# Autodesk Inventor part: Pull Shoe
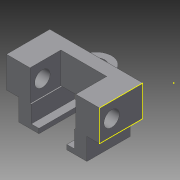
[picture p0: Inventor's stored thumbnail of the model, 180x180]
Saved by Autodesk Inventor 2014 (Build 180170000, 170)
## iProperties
Created: 2013-11
Part Number: Pull Shoe
Material: Generic
Document SubType Name: Modeling
Designer: 603839
Density: 1 g/cm^3
Appearance: Default
Mass: 5.74904 g
Surface Area: 34.2005 cm^2
Volume: 5.74904 cm^3
Author: 603839
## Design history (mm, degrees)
sketch "Sketch1"
  geometry: L1 (-19.05, -6.35)-(19.05, -6.35); L2 (19.05, -6.35)-(19.05, 6.35); L3 (19.05, 6.35)-(-19.05, 6.35); L4 (-19.05, 6.35)-(-19.05, -6.35); L5 (-19.05, -6.35)-(19.05, 6.35); L6 (19.05, -6.35)-(-19.05, 6.35); 1 further point
  constraints: 12 end point, 2 midpoint, 2 parallel, 1 horizontal, 1 perpendicular
  dimensions: "d0" = 38.1 distance of L1.start L1.end; "d1" = 12.7 distance of L2.end L1.end
extrude "Extrusion1" new body sketch "Sketch1" distance "d2" = 25.4; taper "d3" = 0 deg
sketch "Sketch6"
  geometry: L1 (38.1, 0)-(38.1, -25.4) reference; L2 (38.1, 0)-(0, 0) reference; L3 (0, 0)-(0, -25.4) reference; A1 r 20.637 centre (19.05, -20.637) between (38.1, -12.7) and (0, -12.7); 1 further point
  constraints: 3 point on circle, 2 midpoint, 1 centre point
extrude "Extrusion4" cut sketch "Sketch6" distance "d15" = 25.4; taper "d16" = 0 deg
sketch "Sketch7"
  geometry: C1 r 3.175 at (19.05, 25.4); C2 r 5.08 at (19.05, 25.4); 1 further point
  constraints: 2 centre point, 2 coincident
  dimensions: "d17" = 6.35 diameter of C1; "d18" = 10.16 diameter of C2
extrude "Extrusion5" join sketch "Sketch7" distance "d19" = 12.7; taper "d20" = 0 deg
sketch "Sketch8"
  geometry: A1 r 20.637 centre (19.05, 4.763) between (14.009, 24.775) and (0, 12.7) reference; A2 r 20.637 centre (19.05, 4.763) between (38.1, 12.7) and (24.091, 24.775) reference; A3 r 5.08 centre (19.05, 25.4) between (24.091, 24.775) and (14.009, 24.775) reference; A4 r 3.175 centre (19.05, 25.4) between (22.216, 25.156) and (15.884, 25.156) reference; A5 r 20.637 centre (19.05, 4.763) between (22.216, 25.156) and (15.884, 25.156) reference; A6 r 3.175 centre (19.05, 25.4) between (22.216, 25.156) and (15.884, 25.156); A7 r 5.08 centre (19.05, 25.4) between (24.091, 24.775) and (14.009, 24.775); A8 r 20.637 centre (19.05, 4.763) between (24.091, 24.775) and (14.009, 24.775)
  constraints: 13 point on circle, 3 centre point, 3 concentric, 2 coincident
extrude "Extrusion6" cut sketch "Sketch8" distance "d21" = 6.35; taper "d22" = 0 deg
sketch "Sketch13"
  geometry: L1 (18.796, -23.136)-(18.796, 0) reference; L2 (0, 0)-(18.796, 0); L3 (18.796, 0)-(18.796, -7.62); L4 (18.796, -7.62)-(0, -7.62); L5 (0, -7.62)-(0, 0); 1 further point
  constraints: 8 end point, 2 parallel, 1 horizontal, 1 perpendicular, 1 point on line
  dimensions: "d29" = 7.62 distance of L2.end L3.end
extrude "Extrusion10" cut sketch "Sketch13" stored distance "d30" = 2.54; taper "d31" = 0 deg
sketch "Sketch18"
  geometry: L1 (-9.398, -4.763)-(-19.05, -4.763) reference; L2 (-19.05, 7.937)-(19.05, 7.937); A1 r 20.637 centre (0, 0) between (19.05, 7.937) and (-19.05, 7.937) reference; A2 r 20.637 centre (0, 0) between (19.05, 7.937) and (-19.05, 7.937); 1 further point
  constraints: 3 point on circle, 2 end point, 1 centre point, 1 concentric, 1 parallel
extrude "Extrusion13" cut sketch "Sketch18" stored distance "d47" = 2.54; taper "d49" = 0 deg
sketch "Sketch19"
  geometry: A1 r 3.175 centre (19.05, 25.4) between (22.216, 25.156) and (15.884, 25.156) reference; A2 r 20.637 centre (19.05, 4.763) between (24.091, 24.775) and (22.216, 25.156) reference; A3 r 5.08 centre (19.05, 25.4) between (24.091, 24.775) and (14.009, 24.775) reference; A4 r 20.637 centre (19.05, 4.763) between (15.884, 25.156) and (14.009, 24.775) reference
extrude "Extrusion14" cut sketch "Sketch19" stored distance "d50" = 0; taper "d51" = 0 deg
sketch "Sketch21"
  geometry: L1 (28.448, 5.08)-(-9.652, 5.08) reference; L2 (0, 0)-(18.796, 0) reference; C1 r 3.175 at (9.398, 5.398); A1 r 6.35 centre (9.398, 5.08) between (13.208, 0) and (5.588, 0); 1 further point
  constraints: 2 centre point, 2 point on circle, 2 point on line, 1 midpoint
  dimensions: "d52" = 12.7 diameter of A1; "d53" = 6.35 diameter of C1
extrude "Extrusion15" join sketch "Sketch21" stored distance "d54" = 2.54; taper "d55" = 0 deg
sketch "Sketch22"
  geometry: L1 (15.748, -5.08)-(28.448, -5.08) reference; L2 (6.239, -5.08)-(12.557, -5.08) reference; L3 (3.048, -5.08)-(15.748, -5.08); A1 r 6.35 centre (9.398, -5.08) between (3.048, -5.08) and (15.748, -5.08) reference; A2 r 3.175 centre (9.398, -5.398) between (6.239, -5.08) and (12.557, -5.08) reference; A3 r 3.175 centre (9.398, -5.398) between (6.239, -5.08) and (12.557, -5.08); A4 r 6.35 centre (9.398, -5.08) between (3.048, -5.08) and (15.748, -5.08); 2 further points
  constraints: 4 point on circle, 2 centre point, 2 concentric, 2 end point, 1 collinear
sketch "Sketch23"
  geometry: L1 (12.557, 5.08)-(6.239, 5.08) reference; L2 (28.448, 5.08)-(15.748, 5.08) reference; L3 (3.048, 5.08)-(15.748, 5.08); A1 r 3.175 centre (9.398, 5.398) between (12.557, 5.08) and (6.239, 5.08) reference; A2 r 6.35 centre (9.398, 5.08) between (15.748, 5.08) and (3.048, 5.08) reference; 1 further point
  constraints: 2 end point, 1 collinear
extrude "Extrusion16" cut sketch "Sketch23" distance "d56" = 3.048; taper "d57" = 0 deg
extrude "Extrusion17" cut sketch "Sketch22" distance "d58" = 3.048; taper "d59" = 0 deg
sketch "Sketch28"
  geometry: L1 (-19.05, -6.35)-(-9.398, -6.35) reference; L2 (-17.145, -6.35)-(-15.875, -6.35); L3 (-14.605, -6.35)-(-8.255, -6.35); L4 (-15.875, -6.35)-(-14.605, -6.35); L5 (-8.255, -6.35)-(-8.509, -6.35); L6 (-8.255, -6.35)-(-8.89, -6.35); L7 (-8.89, -6.35)-(-8.89, -15.24); L8 (-8.89, -15.24)-(-17.145, -15.24); L9 (-17.145, -15.24)-(-17.145, -13.335); L10 (-17.145, -13.335)-(-13.97, -13.335); L11 (-13.97, -13.335)-(-13.97, -6.35); 1 further point
  constraints: 20 end point, 2 point on line, 1 collinear
  dimensions: "d106" = 1.27 distance of L4.start L4.end; "d115" = 0.635 distance of L3.end L6.end; "d116" = 8.89 distance of L6.end L7.end; "d117" = 8.255 distance of L7.end L8.end; "d118" = 1.905 distance of L8.end L9.end; "d119" = 3.175 distance of L9.end L10.end
extrude "Extrusion27" join sketch "Sketch28" stored distance "d120" = 25.4; taper "d121" = 0 deg
sketch "Sketch29"
  geometry: L1 (-8.89, -6.35)-(-9.398, -6.35) reference; L2 (0, 14.685)-(0, -22.905); L3 (9.398, -6.35)-(9.398, 6.35); L4 (9.398, 6.35)-(19.05, 6.35); L5 (19.05, 6.35)-(19.05, -6.35); L6 (19.05, -6.35)-(13.97, -6.35); L7 (13.97, -6.35)-(13.97, -13.335); L8 (13.97, -13.335)-(17.145, -13.335); L9 (17.145, -13.335)-(17.145, -15.24); L10 (17.145, -15.24)-(8.89, -15.24); L11 (8.89, -15.24)-(8.89, -6.35); L12 (8.89, -6.35)-(9.398, -6.35); 9 further points
  constraints: 22 end point, 10 symmetric about line, 1 perpendicular
extrude "Extrusion28" join sketch "Sketch29" stored distance "d122" = 25.4; taper "d123" = 0 deg
sketch "Sketch32"
  geometry: L1 (9.398, 6.35)-(9.398, -6.35) reference; L2 (8.89, -6.35)-(9.398, -6.35) reference; L3 (8.89, -15.24)-(8.89, -6.35) reference; L4 (17.145, -15.24)-(8.89, -15.24) reference; L5 (17.145, -13.335)-(17.145, -15.24) reference; L6 (13.97, -13.335)-(17.145, -13.335) reference; L7 (13.97, -6.35)-(13.97, -13.335) reference; L8 (13.97, -6.35)-(19.05, -6.35) reference; L9 (19.05, -6.35)-(19.05, 6.35) reference; L10 (19.05, 6.35)-(9.398, 6.35) reference; 1 further point
sketch "Sketch33"
  geometry: L1 (-9.398, -6.35)-(-9.398, 6.35) reference; L2 (-9.398, 6.35)-(-19.05, 6.35) reference; L3 (-19.05, 6.35)-(-19.05, -6.35) reference; L4 (-19.05, -6.35)-(-13.97, -6.35) reference; L5 (-13.97, -6.35)-(-13.97, -13.335) reference; L6 (-13.97, -13.335)-(-17.145, -13.335) reference; L7 (-17.145, -13.335)-(-17.145, -15.24) reference; L8 (-17.145, -15.24)-(-8.89, -15.24) reference; L9 (-8.89, -15.24)-(-8.89, -6.35) reference; L10 (-8.89, -6.35)-(-9.398, -6.35) reference; 1 further point
extrude "Extrusion30" join sketch "Sketch33" distance "d126" = 5.08; taper "d127" = 0 deg
extrude "Extrusion31" join sketch "Sketch32" distance "d128" = 5.08; taper "d129" = 0 deg
sketch "Sketch34"
  geometry: L1 (0, 0)-(0, 12.7) reference; L2 (0, 12.7)-(-17.78, 12.7) reference; L3 (-17.78, 0)-(-17.78, 12.7) reference; L4 (0, 0)-(-17.78, 0) reference; 1 further point
hole "Hole2" diameter "d132" = 6.35; stored, may be unused: countersink angle "d136" = 82 deg, drill point angle "d138" = 118 deg; dims "d130" = 5.08, "d131" = 6.35, "d133" = 19.05, "d134" = 9.525, "d135" = 6.35, "d137" = 25.4
sketch "Sketch35"
  geometry: L1 (-8.89, -15.24)-(-8.89, -6.35) reference; L2 (-8.89, -6.35)-(-9.398, -6.35) reference; L3 (-8.89, -15.24)-(-5.715, -15.24); L4 (-8.89, -15.24)-(-5.715, -15.24); L5 (-5.715, -15.24)-(-5.715, -13.335); L6 (-5.715, -13.335)-(-8.89, -13.335); 1 further point
  constraints: 8 end point, 2 perpendicular, 1 collinear, 1 horizontal, 1 parallel, 1 point on line
  dimensions: "d139" = 3.175 distance of L1.start L3.end; "d140" = 0 distance between parallel lines of L4 L3 (derived)
sketch "Sketch36"
  geometry: L1 (8.89, -6.35)-(8.89, -15.24) reference; L2 (19.05, 6.35)-(9.398, 6.35) reference; L3 (8.89, -15.24)-(5.715, -15.24); L4 (5.715, -15.24)-(5.715, -13.335); L5 (5.715, -13.335)-(8.89, -13.335); 1 further point
  constraints: 6 end point, 2 perpendicular, 1 parallel, 1 point on line
  dimensions: "d141" = 3.175 distance of L1.end L3.end
extrude "Extrusion32" join sketch "Sketch35" stored distance "d142" = 5.08; taper "d143" = 0 deg
extrude "Extrusion33" join sketch "Sketch36" stored distance "d144" = 5.08; taper "d145" = 0 deg
sketch "Sketch37"
  geometry: L1 (-13.97, -13.335)-(-17.145, -13.335) reference; L2 (-17.145, -13.335)-(-17.145, -15.24) reference; L3 (-17.145, -15.24)-(-5.715, -15.24) reference; L4 (-13.97, -13.335)-(-13.97, -15.24); 1 further point
  constraints: 2 end point, 1 perpendicular, 1 point on line
extrude "Extrusion34" cut sketch "Sketch37" stored distance "d146" = 5.08; taper "d147" = 0 deg
sketch "Sketch39"
  geometry: L1 (5.715, -15.24)-(17.145, -15.24) reference; L2 (17.145, -15.24)-(17.145, -13.335) reference; L3 (17.145, -13.335)-(13.97, -13.335) reference; L4 (13.97, -13.335)-(13.97, -15.24); 1 further point
  constraints: 2 end point, 1 perpendicular, 1 point on line
extrude "Extrusion35" cut sketch "Sketch39" stored distance "d148" = 5.08; taper "d149" = 0 deg
body "Solid1"
